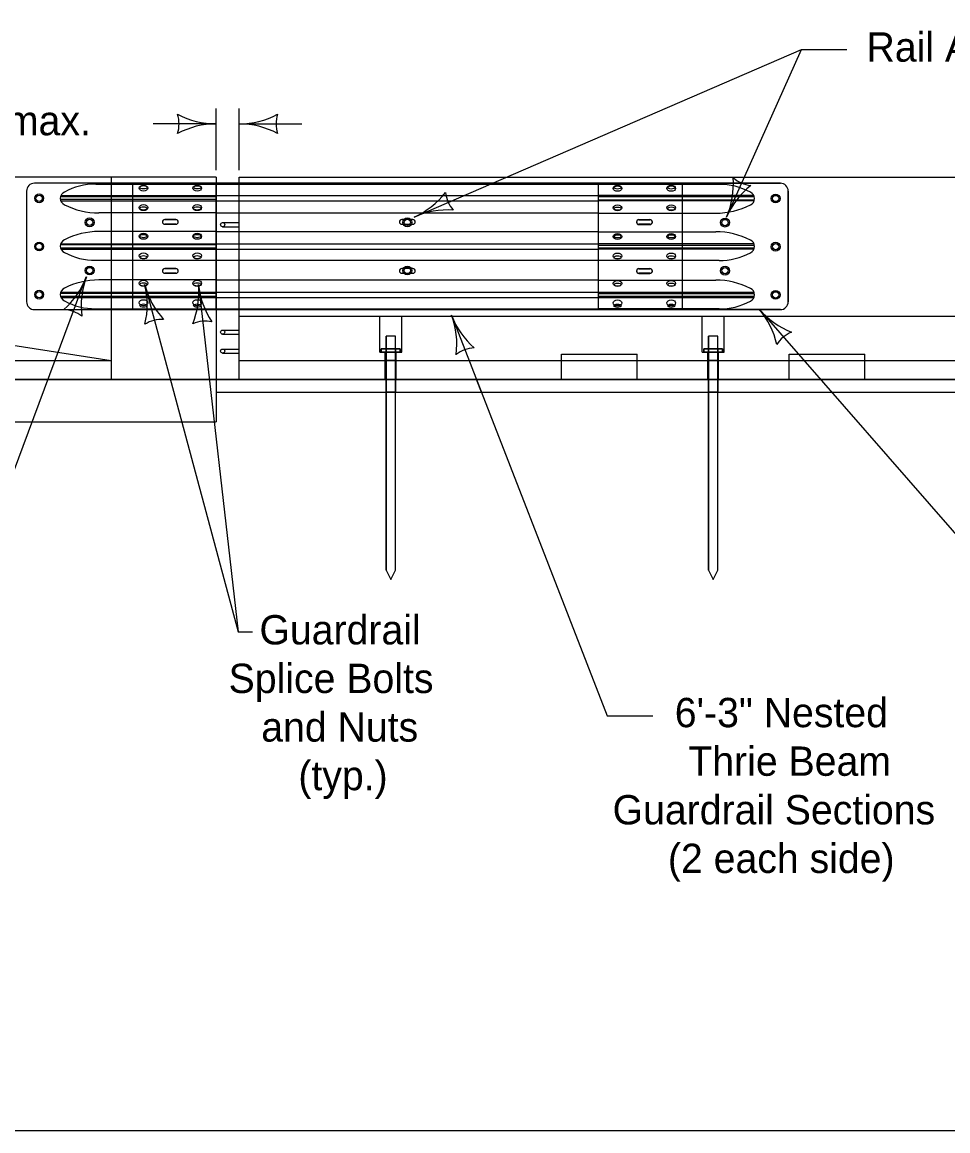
# Model space of a CAD drawing. Extents: x 10028 to 81668, y 3581 to 11018.
# Drawn here: x 17657 to 18137, y 7924 to 8499 of the extents above; entities that cross this region are included whole.
import ezdxf

# ---------------------------------------------------------------- set-up
doc = ezdxf.new("R2010")
doc.units = 0
for name, color, linetype in [('conPaving', 7, 'Continuous'), ('dsnCellsNorthArrow', 7, 'Continuous'), ('dsnTextTabulation', 7, 'Continuous'), ('Level 41', 7, 'Continuous'), ('Level 9', 7, 'Continuous'), ('SheetBorder', 7, 'Continuous')]:
    doc.layers.add(name, color=color, linetype=linetype)

msp = doc.modelspace()

# ---------------------------------------------------------------- linework, layer by layer
at = {"layer": 'conPaving'}
for p, q in [((17659.29, 8411.28), (17659.29, 8353.94)), ((17757.6, 8415.38), (17663.39, 8415.38)), ((17955.84, 8415.38), (17757.6, 8415.38)), ((18050.05, 8415.38), (17955.84, 8415.38)), ((18054.15, 8353.94), (18054.15, 8411.28)), ((17730.97, 8396.54), (17736.71, 8396.54)), ((17736.71, 8394.08), (17730.97, 8394.08)), ((17976.73, 8396.54), (17982.47, 8396.54)), ((17982.47, 8394.08), (17976.73, 8394.08)), ((17730.97, 8371.14), (17736.71, 8371.14)), ((17976.73, 8371.14), (17982.47, 8371.14)), ((17736.71, 8368.68), (17730.97, 8368.68)), ((17982.47, 8368.68), (17976.73, 8368.68)), ((17663.39, 8349.84), (17757.6, 8349.84)), ((17757.6, 8349.84), (17955.84, 8349.84)), ((17955.84, 8349.84), (18050.05, 8349.84)), ((17757.96, 8313.61), (17757.59, 8313.61)), ((17757.59, 8313.61), (17757.59, 8307.05)), ((17845.65, 8313.61), (17757.96, 8313.61)), ((17845.65, 8307.05), (17845.65, 8313.61)), ((17850.94, 8313.61), (17850.57, 8313.61)), ((17850.57, 8313.61), (17850.57, 8307.05)), ((17892.58, 8313.61), (17850.94, 8313.61)), ((17892.58, 8313.61), (17895.13, 8307.05)), ((17895.13, 8307.05), (17892.58, 8313.61)), ((18012.77, 8307.05), (18012.77, 8313.61)), ((18018.06, 8313.61), (18017.69, 8313.61)), ((18017.69, 8313.61), (18017.69, 8307.05)), ((18179.51, 8313.61), (18093.87, 8313.61)), ((17757.59, 8307.05), (17845.65, 8307.05)), ((17850.57, 8307.05), (17895.13, 8307.05)), ((17895.13, 8307.05), (18012.77, 8307.05)), ((18017.69, 8307.05), (18179.89, 8307.05))]:
    msp.add_line(p, q, dxfattribs=at)
for points in [[(18012.77, 8313.61), (18012.4, 8313.61), (17975.91, 8313.61), (17936.58, 8313.61), (17892.58, 8313.61)], [(18093.87, 8313.61), (18054.55, 8313.61), (18018.06, 8313.61)]]:
    msp.add_lwpolyline(points, dxfattribs=at)
for centre, radius, start, end in [((17663.39, 8411.28), 4.1, 90, 180), ((18050.05, 8411.28), 4.1, 0, 90), ((17730.97, 8395.31), 1.23, 90, 270), ((17736.71, 8395.31), 1.23, 270, 90), ((17976.73, 8395.31), 1.23, 90, 270), ((17982.47, 8395.31), 1.23, 270, 90), ((17730.97, 8369.91), 1.23, 90, 270), ((17736.71, 8369.91), 1.23, 270, 90), ((17976.73, 8369.91), 1.23, 90, 270), ((17982.47, 8369.91), 1.23, 270, 90), ((17663.39, 8353.94), 4.1, 180, 270), ((18050.05, 8353.94), 4.1, 270, 0)]:
    msp.add_arc(centre, radius, start, end, dxfattribs=at)
at = {"layer": 'dsnCellsNorthArrow'}
msp.add_line((17757.55, 8313.61), (17508.52, 8313.61), dxfattribs=at)
at = {"layer": 'dsnTextTabulation'}
for p, q in [((17860.22, 8397.87), (18060.99, 8484.78)), ((18022.21, 8397.87), (18060.99, 8484.78)), ((18060.99, 8484.78), (18084.59, 8484.78)), ((17757.59, 8422.14), (17757.59, 8454.2)), ((17769.47, 8422.14), (17769.47, 8454.2)), ((17757.59, 8446.16), (17725.02, 8446.16)), ((17769.47, 8446.16), (17802.03, 8446.16)), ((17757.59, 8418.46), (17508.52, 8418.46)), ((17703.15, 8418.46), (17703.15, 8313.61)), ((17757.59, 8418.46), (17757.59, 8313.61)), ((17769.47, 8313.85), (17769.47, 8418.46)), ((17769.47, 8418.46), (18260.99, 8418.46)), ((17602.63, 8132.06), (17690.3, 8366.86)), ((17720.54, 8362.89), (17769.07, 8182.83)), ((17748.38, 8362.89), (17769.07, 8182.83)), ((17703.15, 8323.37), (17508.52, 8353.62)), ((18039.03, 8350.15), (18203.23, 8161.81)), ((17769.47, 8346.37), (18260.99, 8346.37)), ((17879.61, 8346.97), (17960.36, 8139.23)), ((17936.58, 8326.71), (17975.91, 8326.71)), ((18054.55, 8326.71), (18093.87, 8326.71)), ((17703.15, 8323.37), (17508.52, 8323.37)), ((17769.47, 8323.44), (18260.99, 8323.44)), ((17936.58, 8313.61), (17936.58, 8323.44)), ((17975.91, 8313.61), (17975.91, 8323.44)), ((18054.55, 8313.61), (18054.55, 8323.44)), ((18093.87, 8313.61), (18093.87, 8323.44)), ((17769.71, 8313.61), (17936.58, 8313.61)), ((17975.91, 8313.61), (18054.55, 8313.61)), ((18093.87, 8313.61), (18260.74, 8313.61)), ((17769.07, 8182.83), (17776.36, 8182.83)), ((17960.36, 8139.23), (17983.97, 8139.23))]:
    msp.add_line(p, q, dxfattribs=at)
for centre, radius, start, end in [((17721.95, 8446.16), 16.42, 342.26665, 17.73335), ((17757.59, 8488.66), 42.5, 241.92751, 270), ((17721.95, 8446.16), 16.42, 342.26665, 17.73335), ((17757.59, 8488.66), 42.5, 241.92751, 270), ((17769.47, 8488.66), 42.5, 270, 298.07249), ((17769.47, 8488.66), 42.5, 270, 298.07249), ((17805.1, 8446.16), 16.42, 162.26665, 197.73335), ((17805.1, 8446.16), 16.42, 162.26665, 197.73335), ((17757.59, 8403.66), 42.5, 90, 118.07249), ((17757.59, 8403.66), 42.5, 90, 118.07249), ((17769.47, 8403.66), 42.5, 61.92751, 90), ((17769.47, 8403.66), 42.5, 61.92751, 90), ((17983.2, 8414.75), 42.5, 336.60184, 4.67433), ((18036.36, 8430.58), 16.42, 228.86849, 264.33519), ((17842.9, 8436.68), 42.5, 294.05555, 322.12804), ((17892.76, 8412.4), 16.42, 186.3222, 221.7889), ((18061.21, 8381), 42.5, 128.52935, 156.60184), ((17877.55, 8359.06), 42.5, 85.98306, 114.05555), ((17650.49, 8381.73), 42.5, 311.45357, 339.52606), ((17730.12, 8352), 42.5, 159.52606, 187.59855), ((17679.38, 8352.29), 42.5, 346.36285, 14.43534), ((17761.7, 8373.48), 42.5, 194.43534, 222.50783), ((17706.1, 8358.52), 42.5, 337.83385, 5.90634), ((17790.65, 8367.27), 42.5, 185.90634, 213.97883), ((17677.84, 8333.48), 16.42, 51.79271, 87.25941), ((18006.68, 8322.59), 42.5, 12.36113, 40.43362), ((18071.38, 8377.71), 42.5, 220.43362, 248.50611), ((17729.42, 8328.37), 16.42, 86.70199, 122.16869), ((17752.04, 8327.45), 16.42, 78.17299, 113.63969), ((17839.83, 8332.02), 42.5, 352.52075, 20.59324), ((17919.39, 8361.92), 42.5, 200.59324, 228.66573), ((18062.14, 8323.03), 16.42, 112.70027, 148.16697), ((17892.14, 8313.61), 16.42, 92.85989, 128.32659)]:
    msp.add_arc(centre, radius, start, end, dxfattribs=at)
at = {"layer": 'Level 41'}
for p, q in [((17760.96, 8394.95), (17769.47, 8394.95)), ((17760.96, 8392.83), (17769.47, 8392.83)), ((17842.45, 8327.81), (17842.45, 8346.37)), ((17853.77, 8327.81), (17853.77, 8346.37)), ((18009.57, 8327.81), (18009.57, 8346.37)), ((18020.89, 8327.81), (18020.89, 8346.37)), ((17760.96, 8339.24), (17769.46, 8339.24)), ((17760.96, 8337.12), (17769.46, 8337.12)), ((17760.96, 8329.41), (17769.46, 8329.41)), ((17760.96, 8327.29), (17769.46, 8327.29)), ((17842.45, 8327.81), (17853.77, 8327.81)), ((17845.28, 8313.61), (17845.28, 8327.81)), ((17850.94, 8313.61), (17850.94, 8327.81)), ((18009.57, 8327.81), (18020.89, 8327.81)), ((18012.4, 8313.61), (18012.4, 8327.81)), ((18018.06, 8313.61), (18018.06, 8327.81))]:
    msp.add_line(p, q, dxfattribs=at)
for centre in [(17760.96, 8393.89), (17760.96, 8338.18), (17760.96, 8328.35)]:
    msp.add_circle(centre, 1.06, dxfattribs=at)
at = {"layer": 'Level 9'}
for p, q in [((17659.29, 8411.28), (17659.29, 8353.94)), ((17659.29, 8411.28), (17659.29, 8353.94)), ((17757.6, 8415.38), (17663.39, 8415.38)), ((17757.6, 8415.38), (17663.39, 8415.38)), ((17714.18, 8415.38), (17714.18, 8349.84)), ((17757.6, 8349.84), (17757.6, 8415.38)), ((17955.84, 8415.38), (18050.05, 8415.38)), ((17955.84, 8349.84), (17955.84, 8415.38)), ((17999.26, 8349.73), (17999.26, 8415.27)), ((18054.15, 8411.28), (18054.15, 8353.94)), ((18054.15, 8411.28), (18054.15, 8353.94)), ((17757.6, 8406.93), (17676.83, 8406.93)), ((17676.9, 8408.46), (17757.6, 8408.46)), ((17676.99, 8406.32), (17757.6, 8406.32)), ((17677.13, 8409.08), (17757.6, 8409.08)), ((18036.31, 8408.96), (17955.84, 8408.96)), ((18036.53, 8408.35), (17955.84, 8408.35)), ((17955.84, 8406.82), (18036.6, 8406.82)), ((18036.44, 8406.21), (17955.84, 8406.21)), ((17757.6, 8383.38), (17676.83, 8383.38)), ((17676.9, 8381.84), (17757.6, 8381.84)), ((17676.99, 8383.99), (17757.6, 8383.99)), ((18036.44, 8383.88), (17955.84, 8383.88)), ((17955.84, 8383.27), (18036.6, 8383.27)), ((17677.13, 8381.23), (17757.6, 8381.23)), ((18036.53, 8381.73), (17955.84, 8381.73)), ((18036.31, 8381.12), (17955.84, 8381.12)), ((17676.99, 8358.91), (17757.6, 8358.91)), ((17757.6, 8358.29), (17676.83, 8358.29)), ((17676.9, 8356.76), (17757.6, 8356.76)), ((17677.13, 8356.15), (17757.6, 8356.15)), ((18036.44, 8358.79), (17955.84, 8358.79)), ((17955.84, 8358.18), (18036.6, 8358.18)), ((18036.53, 8356.65), (17955.84, 8356.65)), ((18036.31, 8356.04), (17955.84, 8356.04)), ((17663.39, 8349.84), (17757.6, 8349.84)), ((17663.39, 8349.84), (17757.6, 8349.84)), ((17757.6, 8349.84), (17955.84, 8349.84)), ((17757.6, 8349.84), (17955.84, 8349.84)), ((18050.05, 8349.84), (17955.84, 8349.84)), ((17850.57, 8336), (17845.65, 8336)), ((17845.65, 8336), (17845.65, 8329.45)), ((17850.57, 8336), (17845.65, 8336)), ((17845.65, 8214.76), (17845.65, 8336)), ((17850.57, 8329.45), (17850.57, 8336)), ((17850.57, 8214.76), (17850.57, 8336)), ((18017.69, 8336), (18012.77, 8336)), ((18012.77, 8336), (18012.77, 8329.45)), ((18017.69, 8336), (18012.77, 8336)), ((18012.77, 8214.76), (18012.77, 8336)), ((18017.69, 8329.45), (18017.69, 8336)), ((18017.69, 8214.76), (18017.69, 8336)), ((17843.2, 8329.45), (17843.2, 8327.81)), ((17845.65, 8329.45), (17843.2, 8329.45)), ((17843.2, 8327.81), (17843.2, 8329.45)), ((17843.2, 8327.81), (17845.28, 8327.81)), ((17845.28, 8327.81), (17845.65, 8327.81)), ((17850.57, 8329.45), (17845.65, 8329.45)), ((17845.65, 8329.45), (17845.65, 8327.81)), ((17845.65, 8327.81), (17845.65, 8329.45)), ((17845.65, 8329.45), (17850.57, 8329.45)), ((17850.57, 8327.81), (17845.65, 8327.81)), ((17845.65, 8327.81), (17845.65, 8323.44)), ((17845.65, 8327.81), (17850.57, 8327.81)), ((17850.57, 8327.81), (17850.57, 8329.45)), ((17850.57, 8329.45), (17850.57, 8327.81)), ((17850.57, 8323.44), (17850.57, 8327.81)), ((17936.58, 8323.44), (17936.58, 8326.71)), ((17975.91, 8323.44), (17975.91, 8326.71)), ((18010.31, 8329.45), (18010.31, 8327.81)), ((18012.77, 8329.45), (18010.31, 8329.45)), ((18010.31, 8327.81), (18010.31, 8329.45)), ((18010.31, 8327.81), (18012.4, 8327.81)), ((18012.4, 8327.81), (18012.77, 8327.81)), ((18017.69, 8329.45), (18012.77, 8329.45)), ((18012.77, 8329.45), (18012.77, 8327.81)), ((18012.77, 8327.81), (18012.77, 8329.45)), ((18012.77, 8329.45), (18017.69, 8329.45)), ((18017.69, 8327.81), (18012.77, 8327.81)), ((18012.77, 8327.81), (18012.77, 8323.44)), ((18012.77, 8327.81), (18017.69, 8327.81)), ((18017.69, 8327.81), (18017.69, 8329.45)), ((18017.69, 8329.45), (18017.69, 8327.81)), ((18017.69, 8323.44), (18017.69, 8327.81)), ((18054.55, 8323.44), (18054.55, 8326.71)), ((18093.87, 8323.44), (18093.87, 8326.71)), ((17850.57, 8323.44), (17845.65, 8323.44)), ((17845.65, 8323.44), (17845.65, 8313.61)), ((17845.65, 8323.44), (17850.57, 8323.44)), ((17850.57, 8313.61), (17850.57, 8323.44)), ((17936.58, 8323.44), (17975.91, 8323.44)), ((18017.69, 8323.44), (18012.77, 8323.44)), ((18012.77, 8323.44), (18012.77, 8313.61)), ((18012.77, 8323.44), (18017.69, 8323.44)), ((18017.69, 8313.61), (18017.69, 8323.44)), ((18054.55, 8323.44), (18093.87, 8323.44)), ((17461.95, 8313.61), (20253.11, 8313.61)), ((17757.59, 8313.61), (17757.59, 8307.05)), ((17757.59, 8313.61), (17757.59, 8291.66)), ((17769.47, 8313.85), (17769.71, 8313.61)), ((17850.57, 8313.61), (17845.65, 8313.61)), ((17845.65, 8313.61), (17845.65, 8307.05)), ((17845.65, 8313.61), (17850.57, 8313.61)), ((17850.57, 8307.05), (17850.57, 8313.61)), ((18017.69, 8313.61), (18012.77, 8313.61)), ((18012.77, 8313.61), (18012.77, 8307.05)), ((18012.77, 8313.61), (18017.69, 8313.61)), ((18017.69, 8307.05), (18017.69, 8313.61)), ((17757.59, 8307.05), (19777.13, 8307.05)), ((17850.57, 8307.05), (17845.65, 8307.05)), ((17845.65, 8307.05), (17845.65, 8214.76)), ((17845.65, 8307.05), (17850.57, 8307.05)), ((17850.57, 8214.76), (17850.57, 8307.05)), ((18017.69, 8307.05), (18012.77, 8307.05)), ((18012.77, 8307.05), (18012.77, 8214.76)), ((18012.77, 8307.05), (18017.69, 8307.05)), ((18017.69, 8214.76), (18017.69, 8307.05)), ((17450.88, 8291.66), (17757.59, 8291.66)), ((17845.65, 8214.76), (17848.11, 8209.84)), ((17845.65, 8214.76), (17848.11, 8209.84)), ((17848.11, 8209.84), (17850.57, 8214.76)), ((17848.11, 8209.84), (17850.57, 8214.76)), ((18012.77, 8214.76), (18015.23, 8209.84)), ((18012.77, 8214.76), (18015.23, 8209.84)), ((18015.23, 8209.84), (18017.69, 8214.76)), ((18015.23, 8209.84), (18017.69, 8214.76))]:
    msp.add_line(p, q, dxfattribs=at)
for points in [[(17695.19, 8414.88), (17757.6, 8414.88)], [(17757.6, 8415.38), (17955.84, 8415.38)], [(17757.6, 8414.88), (17955.84, 8414.88)], [(18018.25, 8414.77), (17955.84, 8414.77)], [(17757.6, 8409.08), (17955.84, 8409.08)], [(17757.6, 8406.32), (17955.84, 8406.32)], [(17757.6, 8399.97), (17696.82, 8399.97)], [(17757.6, 8399.97), (17955.84, 8399.97)], [(17955.84, 8399.86), (18016.62, 8399.86)], [(17736.71, 8396.54), (17730.97, 8396.54)], [(17736.71, 8396.54), (17730.97, 8396.54)], [(17730.97, 8394.08), (17736.71, 8394.08)], [(17730.97, 8394.08), (17736.71, 8394.08)], [(17859.59, 8396.54), (17853.85, 8396.54)], [(17859.59, 8396.54), (17853.85, 8396.54)], [(17853.85, 8394.08), (17859.59, 8394.08)], [(17853.85, 8394.08), (17859.59, 8394.08)], [(17976.73, 8396.43), (17982.47, 8396.43)], [(17982.47, 8396.43), (17976.73, 8396.43)], [(17976.73, 8396.43), (17982.47, 8396.43)], [(17982.47, 8396.43), (17976.73, 8396.43)], [(17982.47, 8393.97), (17976.73, 8393.97)], [(17976.73, 8393.97), (17982.47, 8393.97)], [(17982.47, 8393.97), (17976.73, 8393.97)], [(17976.73, 8393.97), (17982.47, 8393.97)], [(17757.6, 8390.34), (17696.82, 8390.34)], [(17757.6, 8390.34), (17955.84, 8390.34)], [(17955.84, 8390.23), (18016.62, 8390.23)], [(17757.6, 8383.99), (17955.84, 8383.99)], [(17757.6, 8381.23), (17955.84, 8381.23)], [(17695.19, 8375.42), (17757.6, 8375.42)], [(17736.71, 8371.14), (17730.97, 8371.14)], [(17736.71, 8371.14), (17730.97, 8371.14)], [(17757.6, 8375.42), (17955.84, 8375.42)], [(17859.59, 8371.14), (17853.85, 8371.14)], [(17859.59, 8371.14), (17853.85, 8371.14)], [(18018.25, 8375.31), (17955.84, 8375.31)], [(17976.73, 8371.03), (17982.47, 8371.03)], [(17982.47, 8371.03), (17976.73, 8371.03)], [(17976.73, 8371.03), (17982.47, 8371.03)], [(17982.47, 8371.03), (17976.73, 8371.03)], [(17757.6, 8365.26), (17696.82, 8365.26)], [(17730.97, 8368.68), (17736.71, 8368.68)], [(17730.97, 8368.68), (17736.71, 8368.68)], [(17757.6, 8365.26), (17955.84, 8365.26)], [(17853.85, 8368.68), (17859.59, 8368.68)], [(17853.85, 8368.68), (17859.59, 8368.68)], [(17955.84, 8365.14), (18016.62, 8365.14)], [(17982.47, 8368.57), (17976.73, 8368.57)], [(17976.73, 8368.57), (17982.47, 8368.57)], [(17982.47, 8368.57), (17976.73, 8368.57)], [(17976.73, 8368.57), (17982.47, 8368.57)], [(17757.6, 8358.91), (17955.84, 8358.91)], [(17757.6, 8356.15), (17955.84, 8356.15)], [(17695.19, 8350.34), (17757.6, 8350.34)], [(17757.6, 8350.34), (17955.84, 8350.34)], [(18018.25, 8350.23), (17955.84, 8350.23)], [(17843.2, 8329.45), (17853.03, 8329.45), (17853.03, 8327.81), (17843.2, 8327.81)], [(17853.03, 8327.81), (17853.03, 8329.45), (17850.57, 8329.45)], [(17850.57, 8327.81), (17850.94, 8327.81), (17853.03, 8327.81)], [(18010.31, 8329.45), (18020.14, 8329.45), (18020.14, 8327.81), (18010.31, 8327.81)], [(18020.14, 8327.81), (18020.14, 8329.45), (18017.69, 8329.45)], [(18017.69, 8327.81), (18018.06, 8327.81), (18020.14, 8327.81)]]:
    msp.add_lwpolyline(points, dxfattribs=at)
for centre, radius in [((17665.84, 8407.58), 2.3), ((17665.84, 8407.58), 1.64), ((17665.84, 8407.58), 1.64), ((18047.59, 8407.47), 2.3), ((18047.59, 8407.47), 1.64), ((18047.59, 8407.47), 1.64), ((17692.06, 8395.1), 2.3), ((17692.06, 8395.1), 1.64), ((17692.06, 8395.1), 1.64), ((17856.72, 8395.1), 2.3), ((17856.72, 8395.1), 1.64), ((17856.72, 8395.1), 1.64), ((18021.38, 8394.99), 2.3), ((18021.38, 8394.99), 1.64), ((18021.38, 8394.99), 1.64), ((17665.84, 8382.59), 2.3), ((17665.84, 8382.59), 1.64), ((17665.84, 8382.59), 1.64), ((18047.59, 8382.48), 2.3), ((18047.59, 8382.48), 1.64), ((18047.59, 8382.48), 1.64), ((17692.06, 8370.12), 2.3), ((17692.06, 8370.12), 1.64), ((17692.06, 8370.12), 1.64), ((17856.72, 8370.12), 2.3), ((17856.72, 8370.12), 1.64), ((17856.72, 8370.12), 1.64), ((18021.38, 8370.01), 2.3), ((18021.38, 8370.01), 1.64), ((18021.38, 8370.01), 1.64), ((17665.84, 8357.63), 2.3), ((17665.84, 8357.63), 1.64), ((17665.84, 8357.63), 1.64), ((18047.59, 8357.51), 2.3), ((18047.59, 8357.51), 1.64), ((18047.59, 8357.51), 1.64)]:
    msp.add_circle(centre, radius, dxfattribs=at)
for centre, radius, start, end in [((17663.39, 8411.28), 4.1, 90, 180), ((17663.39, 8411.28), 4.1, 90, 180), ((17680.37, 8407.53), 3.59, 113.8801, 246.1199), ((17694.72, 8382.18), 32.71, 89.18232, 118.89051), ((18018.72, 8382.07), 32.71, 61.10949, 90.81768), ((18033.07, 8407.42), 3.59, 293.8801, 66.1199), ((18050.05, 8411.28), 4.1, 0, 90), ((18050.05, 8411.28), 4.1, 0, 90), ((17696.78, 8439.34), 39.37, 243.01498, 270.05598), ((18016.65, 8439.23), 39.37, 269.94402, 296.98502), ((17730.97, 8395.31), 1.23, 90, 270), ((17730.97, 8395.31), 1.23, 90, 270), ((17736.71, 8395.31), 1.23, 270, 90), ((17736.71, 8395.31), 1.23, 270, 90), ((17853.85, 8395.31), 1.23, 90, 270), ((17853.85, 8395.31), 1.23, 90, 270), ((17859.59, 8395.31), 1.23, 270, 90), ((17859.59, 8395.31), 1.23, 270, 90), ((17976.73, 8395.2), 1.23, 90, 270), ((17976.73, 8395.2), 1.23, 90, 270), ((17976.73, 8395.2), 1.23, 90, 270), ((17976.73, 8395.2), 1.23, 90, 270), ((17982.47, 8395.2), 1.23, 270, 90), ((17982.47, 8395.2), 1.23, 270, 90), ((17982.47, 8395.2), 1.23, 270, 90), ((17982.47, 8395.2), 1.23, 270, 90), ((17696.78, 8350.97), 39.37, 89.94402, 116.98502), ((18016.65, 8350.86), 39.37, 63.01498, 90.05598), ((17680.37, 8382.77), 3.59, 113.8801, 246.1199), ((18033.07, 8382.66), 3.59, 293.8801, 66.1199), ((17694.72, 8408.13), 32.71, 241.10949, 270.81768), ((18018.72, 8408.02), 32.71, 269.18232, 298.89051), ((17730.97, 8369.91), 1.23, 90, 270), ((17730.97, 8369.91), 1.23, 90, 270), ((17736.71, 8369.91), 1.23, 270, 90), ((17736.71, 8369.91), 1.23, 270, 90), ((17853.85, 8369.91), 1.23, 90, 270), ((17853.85, 8369.91), 1.23, 90, 270), ((17859.59, 8369.91), 1.23, 270, 90), ((17859.59, 8369.91), 1.23, 270, 90), ((17976.73, 8369.8), 1.23, 90, 270), ((17976.73, 8369.8), 1.23, 90, 270), ((17976.73, 8369.8), 1.23, 90, 270), ((17976.73, 8369.8), 1.23, 90, 270), ((17982.47, 8369.8), 1.23, 270, 90), ((17982.47, 8369.8), 1.23, 270, 90), ((17982.47, 8369.8), 1.23, 270, 90), ((17982.47, 8369.8), 1.23, 270, 90), ((17696.78, 8325.88), 39.37, 89.94402, 116.98502), ((18016.65, 8325.77), 39.37, 63.01498, 90.05598), ((17680.37, 8357.69), 3.59, 113.8801, 246.1199), ((18033.07, 8357.58), 3.59, 293.8801, 66.1199), ((17663.39, 8353.94), 4.1, 180, 270), ((17663.39, 8353.94), 4.1, 180, 270), ((17694.72, 8383.04), 32.71, 241.10949, 270.81768), ((18018.72, 8382.93), 32.71, 269.18232, 298.89051), ((18050.05, 8353.94), 4.1, 270, 0), ((18050.05, 8353.94), 4.1, 270, 0)]:
    msp.add_arc(centre, radius, start, end, dxfattribs=at)
for centre, major_axis, ratio in [((17719.94, 8412.85), (-2.26, 0), 0.685714), ((17719.93, 8413.29), (-1.84, 0), 0.456281), ((17747.8, 8412.85), (-2.26, 0), 0.685714), ((17747.76, 8413.28), (-1.84, 0), 0.456281), ((17965.63, 8412.74), (2.26, 0), 0.685714), ((17965.67, 8413.17), (1.84, 0), 0.456281), ((17993.5, 8412.74), (2.26, 0), 0.685714), ((17993.51, 8413.18), (1.84, 0), 0.456281), ((17719.94, 8402.76), (-2.26, 0), 0.685714), ((17719.91, 8402.34), (-1.84, 0), 0.456281), ((17747.8, 8402.76), (-2.26, 0), 0.685714), ((17747.75, 8402.33), (-1.84, 0), 0.456281), ((17965.63, 8402.65), (2.26, 0), 0.685714), ((17965.69, 8402.22), (1.84, 0), 0.456281), ((17993.5, 8402.65), (2.26, 0), 0.685714), ((17993.53, 8402.23), (1.84, 0), 0.456281), ((17719.94, 8387.86), (-2.26, 0), 0.685714), ((17719.91, 8387.97), (-1.84, 0), 0.456281), ((17747.8, 8387.86), (-2.26, 0), 0.685714), ((17747.75, 8387.98), (-1.84, 0), 0.456281), ((17965.63, 8387.75), (2.26, 0), 0.685714), ((17965.69, 8387.87), (1.84, 0), 0.456281), ((17993.5, 8387.75), (2.26, 0), 0.685714), ((17993.53, 8387.86), (1.84, 0), 0.456281), ((17719.94, 8377.76), (-2.26, 0), 0.685714), ((17719.93, 8377.02), (-1.84, 0), 0.456281), ((17747.8, 8377.76), (-2.26, 0), 0.685714), ((17747.76, 8377.03), (-1.84, 0), 0.456281), ((17965.63, 8377.65), (2.26, 0), 0.685714), ((17965.67, 8376.92), (1.84, 0), 0.456281), ((17993.5, 8377.65), (2.26, 0), 0.685714), ((17993.51, 8376.91), (1.84, 0), 0.456281), ((17719.94, 8363.52), (-2.26, 0), 0.685714), ((17747.8, 8363.52), (-2.26, 0), 0.685714), ((17965.63, 8363.41), (2.26, 0), 0.685714), ((17993.5, 8363.41), (2.26, 0), 0.685714), ((17719.91, 8362.89), (-1.84, 0), 0.456281), ((17747.75, 8362.89), (-1.84, 0), 0.456281), ((17965.69, 8362.78), (1.84, 0), 0.456281), ((17993.53, 8362.78), (1.84, 0), 0.456281), ((17719.94, 8353.42), (-2.26, 0), 0.685714), ((17747.8, 8353.42), (-2.26, 0), 0.685714), ((17965.63, 8353.31), (2.26, 0), 0.685714), ((17993.5, 8353.31), (2.26, 0), 0.685714), ((17719.93, 8351.93), (-1.84, 0), 0.456281), ((17747.76, 8351.94), (-1.84, 0), 0.456281), ((17965.67, 8351.83), (1.84, 0), 0.456281), ((17993.51, 8351.82), (1.84, 0), 0.456281)]:
    msp.add_ellipse(centre, major_axis=major_axis, ratio=ratio, dxfattribs=at)
at = {"layer": 'SheetBorder'}
msp.add_lwpolyline([(17332.52, 9944.02), (20467.53, 9944.02), (20467.53, 7924.02), (17332.52, 7924.02)], close=True, dxfattribs=at)

# ---------------------------------------------------------------- texts
at = {"layer": 'dsnCellsNorthArrow'}
for s, p in [('Rail Anchor Bolt', (18094.72, 8478.43)), ('4" min., 12" max.', (17539.28, 8440.26)), ('Guardrail', (17780.03, 8176.24)), ('Splice Bolts', (17764.06, 8151.04)), ('6\'-3" Nested', (17995.32, 8133.31)), ('and Nuts', (17780.97, 8125.84)), ('Thrie Beam', (18002.35, 8108.11)), ('(typ.)', (17800.2, 8100.64)), ('Guardrail Sections', (17963.09, 8082.91)), ('(2 each side)', (17991.77, 8057.71))]:
    msp.add_text(s, height=15.2, dxfattribs=at).set_placement(p)

doc.saveas('drawing.dxf')
